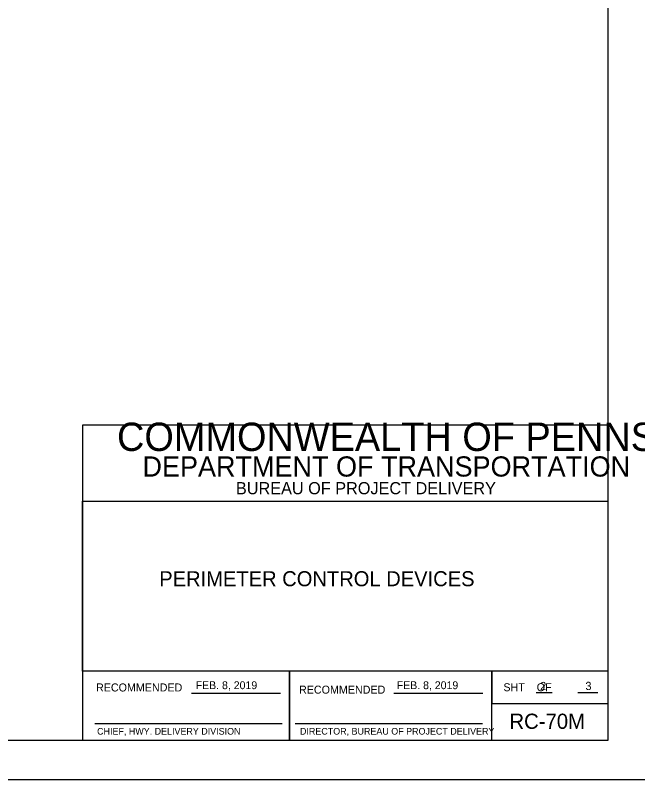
# Model space of a CAD drawing. Extents: x 636462 to 639049, y 299944 to 300538.
# Drawn here: x 637903.4 to 638140.2, y 299944.4 to 300235.4 of the extents above; entities that cross this region are included whole.
import ezdxf

# ---------------------------------------------------------------- set-up
doc = ezdxf.new("R2010")
doc.units = 0
for name, color, linetype in [('1', 7, 'Continuous'), ('Default', 7, 'Continuous'), ('PLT-BNDY', 7, 'Continuous')]:
    doc.layers.add(name, color=color, linetype=linetype)

msp = doc.modelspace()

# ---------------------------------------------------------------- linework, layer by layer
at = {"layer": '1'}
for p, q in [((637970.38, 299977.44), (638004.27, 299977.44)), ((638047.38, 299977.44), (638081.25, 299977.44)), ((638101.54, 299977.66), (638107.68, 299977.66)), ((638117.35, 299977.66), (638124.99, 299977.66)), ((637933.68, 299965.87), (638004.93, 299965.87)), ((638009.85, 299965.87), (638081.19, 299965.87))]:
    msp.add_line(p, q, dxfattribs=at)
msp.add_lwpolyline([(638128.91, 299959.45), (638128.91, 300523.45), (637342.91, 300523.45), (637342.91, 299959.45), (638128.91, 299959.45), (638128.91, 299985.81), (637928.91, 299985.81), (637928.91, 300050.49), (638128.91, 300050.49), (638128.91, 300079.45), (637928.91, 300079.45), (637928.91, 299959.45), (638007.72, 299959.45), (638007.72, 299985.81), (638007.72, 299959.45), (638084.72, 299959.45), (638084.72, 299985.81), (638084.72, 299973.49), (638128.91, 299973.49)], dxfattribs=at)
at = {"layer": 'PLT-BNDY'}
msp.add_lwpolyline([(637302.91, 300538.45), (638143.91, 300538.45), (638143.91, 299944.45), (637302.91, 299944.45)], close=True, dxfattribs=at)

# ---------------------------------------------------------------- texts
at = {"layer": '1'}
for s, height, p in [('COMMONWEALTH OF PENNSYLVANIA', 10.7834, (637942.07, 300069.59)), ('DEPARTMENT OF TRANSPORTATION', 7.6843, (637951.75, 300059.84)), ('BUREAU OF PROJECT DELIVERY', 4.6221, (637987.32, 300053.11)), ('FEB. 8, 2019', 3, (637971.99, 299978.92)), ('FEB. 8, 2019', 3, (638048.49, 299978.92)), ('2', 3.13, (638103.05, 299978.54)), ('3', 3.13, (638120.28, 299978.59)), ('RECOMMENDED', 3.048, (637934.08, 299978.04)), ('RECOMMENDED', 3.048, (638011.32, 299977.21)), ('SHT    OF', 3.048, (638089.08, 299978.12)), ('APPROVED', 0.0192, (637971.94, 299977.38)), ('APPROVED', 0.0192, (637971.94, 299977.38)), ('APPROVED', 0.0192, (637971.94, 299977.38)), ('APPROVED', 0.0192, (637971.94, 299977.38)), ('CHIEF, HWY. DELIVERY DIVISION', 2.54, (637934.5, 299961.62)), ('DIRECTOR, BUREAU OF PROJECT DELIVERY', 2.54, (638011.69, 299961.62))]:
    msp.add_text(s, height=height, dxfattribs=at).set_placement(p)
at = {"layer": 'Default'}
for s, height, p in [('PERIMETER CONTROL DEVICES', 5.7257, (637958.13, 300018.1)), ('RC-70M', 5.779, (638091.37, 299963.81))]:
    msp.add_text(s, height=height, dxfattribs=at).set_placement(p)

doc.saveas('drawing.dxf')
